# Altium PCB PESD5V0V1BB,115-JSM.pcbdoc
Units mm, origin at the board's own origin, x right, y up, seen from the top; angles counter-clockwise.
Board outline 14.8 x 13.7 mm, 2 copper layers (Top Layer, Bottom Layer), stack 0 mm thick; 1 components, 0 nets, 2 pads, 0 vias.
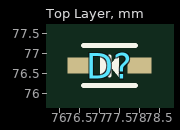
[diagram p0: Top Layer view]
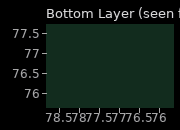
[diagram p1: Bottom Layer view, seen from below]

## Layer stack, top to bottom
Top Layer: signal copper (thickness not stored)
Bottom Layer: signal copper (thickness not stored)

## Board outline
84.65,69.85 69.85,69.85 69.85,83.55 84.65,83.55

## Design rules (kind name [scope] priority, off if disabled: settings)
PasteMaskExpansion "Paste Mask Expansion" [All] p1: expansion=0
SolderMaskExpansion "Solder Mask Expansion" [IsVia] p1: expansion=-25.4 istentingtop=TRUE
SolderMaskExpansion "Solder Mask Expansion" [All] p2: expansion=0.051 istentingtop=FALSE

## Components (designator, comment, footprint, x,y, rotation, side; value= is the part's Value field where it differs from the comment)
D? "PESD5V0V1BB,115-JSM" SOD-523_L1.2-W0.8-LS1.6-BI 77.25,76.7 r0 top

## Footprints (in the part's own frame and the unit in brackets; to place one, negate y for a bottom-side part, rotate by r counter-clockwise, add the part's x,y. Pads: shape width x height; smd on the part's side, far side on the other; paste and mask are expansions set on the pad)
SOD-523_L1.2-W0.8-LS1.6-BI [mm]
  rect 0.6x0.4 smd: 1(-0.75,0) 2(0.75,0)
  silkscreen extent -0.65,-0.5 0.65,0.5

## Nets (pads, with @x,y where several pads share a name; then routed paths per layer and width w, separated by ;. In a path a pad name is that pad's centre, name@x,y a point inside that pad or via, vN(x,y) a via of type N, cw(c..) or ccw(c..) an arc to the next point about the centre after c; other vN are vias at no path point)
pads on no net: D?.1 D?.2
